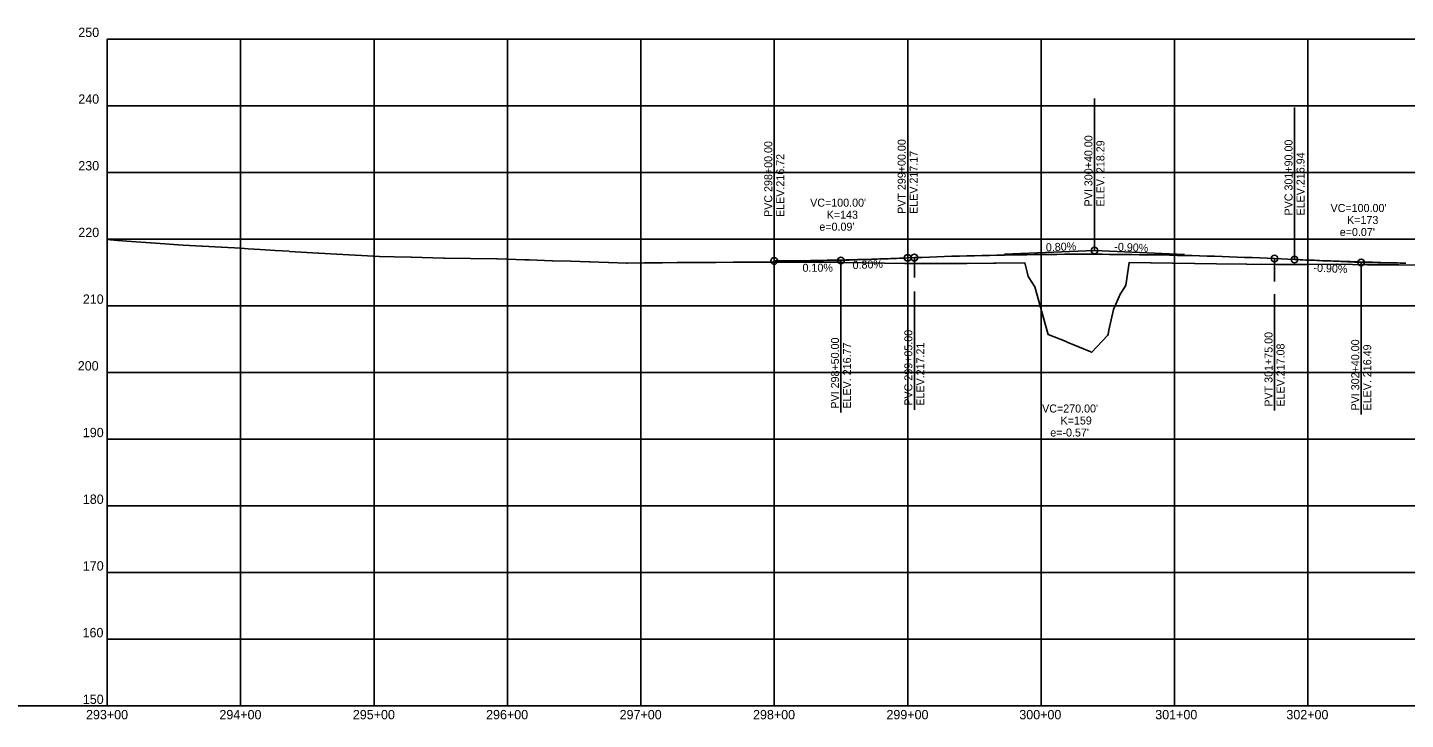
# Model space of a CAD drawing. Extents: x 1138442 to 1165793, y 1654070 to 1657687.
# Drawn here: x 1163494 to 1164527, y 1654670 to 1655189 of the extents above; entities that cross this region are included whole.
import ezdxf

# ---------------------------------------------------------------- set-up
doc = ezdxf.new("R2010")
doc.units = 0
for name, color, linetype in [('B_Dimensions', 7, 'Continuous'), ('R_Axis', 7, 'Continuous'), ('R_Axis Annot', 7, 'Continuous'), ('R_Grid', 7, 'Continuous'), ('R_Horz Alg Annot', 7, 'Continuous'), ('R_No Plot', 7, 'Continuous'), ('R_Proposed Const Limits_Hand', 7, 'Continuous'), ('R_Vert Alg Annot', 7, 'Continuous')]:
    doc.layers.add(name, color=color, linetype=linetype)

msp = doc.modelspace()

# ---------------------------------------------------------------- linework, layer by layer
at = {"layer": 'B_Dimensions'}
for p, q in [((1164153.6, 1655016.3), (1164158.6, 1655016.5)), ((1164226.1, 1655019.2), (1164293.6, 1655021.9)), ((1164293.6, 1655021.9), (1164361.1, 1655018.8)), ((1164428.6, 1655015.8), (1164443.6, 1655015.1)), ((1164078.6, 1655014.1), (1164103.6, 1655014.3)), ((1164103.6, 1655014.3), (1164128.6, 1655015.3)), ((1164468.6, 1655014), (1164493.6, 1655012.9)), ((1164493.6, 1655012.9), (1164518.6, 1655012.4))]:
    msp.add_line(p, q, dxfattribs=at)
for points in [[(1164053.6, 1655014), (1164055.7, 1655014), (1164057.8, 1655014), (1164059.9, 1655014), (1164062, 1655014.1), (1164064, 1655014.1), (1164066.1, 1655014.1), (1164068.2, 1655014.1), (1164070.3, 1655014.1), (1164072.4, 1655014.2), (1164074.5, 1655014.2), (1164076.5, 1655014.2), (1164078.6, 1655014.2), (1164080.7, 1655014.3), (1164082.8, 1655014.3), (1164084.9, 1655014.3), (1164087, 1655014.4), (1164089, 1655014.4), (1164091.1, 1655014.4), (1164093.2, 1655014.5), (1164095.3, 1655014.5), (1164097.4, 1655014.6), (1164099.5, 1655014.6), (1164101.5, 1655014.6), (1164105.7, 1655014.7), (1164107.8, 1655014.8), (1164109.9, 1655014.8), (1164112, 1655014.9), (1164114, 1655014.9), (1164116.1, 1655015), (1164118.2, 1655015.1), (1164120.3, 1655015.1), (1164122.4, 1655015.2), (1164124.5, 1655015.2), (1164126.5, 1655015.3), (1164128.6, 1655015.4), (1164130.7, 1655015.4), (1164132.8, 1655015.5), (1164134.9, 1655015.6), (1164137, 1655015.6), (1164139, 1655015.7), (1164141.1, 1655015.8), (1164143.2, 1655015.9), (1164145.3, 1655015.9), (1164147.4, 1655016), (1164149.5, 1655016.1), (1164151.5, 1655016.2), (1164153.6, 1655016.3)], [(1164158.6, 1655016.5), (1164164.3, 1655016.7), (1164169.9, 1655016.9), (1164175.5, 1655017.1), (1164181.1, 1655017.3), (1164186.8, 1655017.5), (1164192.4, 1655017.6), (1164198, 1655017.8), (1164203.6, 1655017.9), (1164209.3, 1655018.1), (1164214.9, 1655018.2), (1164220.5, 1655018.3), (1164226.1, 1655018.4), (1164231.8, 1655018.5), (1164237.4, 1655018.6), (1164243, 1655018.7), (1164248.6, 1655018.8), (1164254.3, 1655018.8), (1164259.9, 1655018.9), (1164265.5, 1655018.9), (1164271.1, 1655019), (1164276.8, 1655019), (1164282.4, 1655019), (1164288, 1655019), (1164299.3, 1655019), (1164304.9, 1655018.9), (1164310.5, 1655018.9), (1164316.1, 1655018.8), (1164321.8, 1655018.8), (1164327.4, 1655018.7), (1164333, 1655018.6), (1164338.6, 1655018.6), (1164344.3, 1655018.5), (1164349.9, 1655018.3), (1164355.5, 1655018.2), (1164361.1, 1655018.1), (1164366.8, 1655018), (1164372.4, 1655017.8), (1164378, 1655017.7), (1164383.6, 1655017.5), (1164389.3, 1655017.3), (1164394.9, 1655017.1), (1164400.5, 1655016.9), (1164406.1, 1655016.7), (1164411.8, 1655016.5), (1164417.4, 1655016.3), (1164423, 1655016), (1164428.6, 1655015.8)], [(1164443.6, 1655015.1), (1164445.7, 1655015), (1164447.8, 1655014.9), (1164449.9, 1655014.8), (1164452, 1655014.7), (1164454, 1655014.6), (1164456.1, 1655014.6), (1164458.2, 1655014.5), (1164460.3, 1655014.4), (1164462.4, 1655014.3), (1164464.5, 1655014.2), (1164466.5, 1655014.1), (1164468.6, 1655014.1), (1164470.7, 1655014), (1164472.8, 1655013.9), (1164474.9, 1655013.8), (1164477, 1655013.8), (1164479, 1655013.7), (1164481.1, 1655013.6), (1164483.2, 1655013.5), (1164485.3, 1655013.5), (1164487.4, 1655013.4), (1164489.5, 1655013.3), (1164491.5, 1655013.3), (1164495.7, 1655013.2), (1164497.8, 1655013.1), (1164499.9, 1655013), (1164502, 1655013), (1164504, 1655012.9), (1164506.1, 1655012.9), (1164508.2, 1655012.8), (1164510.3, 1655012.7), (1164512.4, 1655012.7), (1164514.5, 1655012.6), (1164516.5, 1655012.6), (1164518.6, 1655012.5), (1164520.7, 1655012.5), (1164522.8, 1655012.4), (1164524.9, 1655012.4), (1164527, 1655012.4)]]:
    msp.add_lwpolyline(points, dxfattribs=at)
at = {"layer": 'R_Axis'}
for q in [(1163553.6, 1655180.4), (1165053.6, 1654680.4)]:
    msp.add_line((1163553.6, 1654680.4), q, dxfattribs=at)
at = {"layer": 'R_Grid'}
for p, q in [((1163553.6, 1655180.4), (1165053.6, 1655180.4)), ((1163553.6, 1655180.4), (1165053.6, 1655180.4)), ((1163653.6, 1654680.4), (1163653.6, 1655180.4)), ((1163753.6, 1654680.4), (1163753.6, 1655180.4)), ((1163853.6, 1654680.4), (1163853.6, 1655180.4)), ((1163953.6, 1654680.4), (1163953.6, 1655180.4)), ((1164053.6, 1654680.4), (1164053.6, 1655180.4)), ((1164153.6, 1654680.4), (1164153.6, 1655180.4)), ((1164253.6, 1654680.4), (1164253.6, 1655180.4)), ((1164353.6, 1654680.4), (1164353.6, 1655180.4)), ((1164453.6, 1654680.4), (1164453.6, 1655180.4)), ((1163553.6, 1655130.4), (1165053.6, 1655130.4)), ((1163553.6, 1655080.4), (1165053.6, 1655080.4)), ((1163553.6, 1655030.4), (1165053.6, 1655030.4)), ((1163553.6, 1654980.4), (1165053.6, 1654980.4)), ((1163553.6, 1654930.4), (1165053.6, 1654930.4)), ((1163553.6, 1654880.4), (1165053.6, 1654880.4)), ((1163553.6, 1654830.4), (1165053.6, 1654830.4)), ((1163553.6, 1654780.4), (1165053.6, 1654780.4)), ((1163553.6, 1654730.4), (1165053.6, 1654730.4))]:
    msp.add_line(p, q, dxfattribs=at)
at = {"layer": 'R_No Plot'}
msp.add_line((1163553.6, 1654680.4), (1161984.5, 1654680.4), dxfattribs=at)
at = {"layer": 'R_Proposed Const Limits_Hand'}
msp.add_lwpolyline([(1163553.6, 1655030), (1163561.2, 1655029.4), (1163561.4, 1655029.4), (1163571.7, 1655028.7), (1163585.9, 1655027.7), (1163586.3, 1655027.7), (1163610.4, 1655025.9), (1163624.4, 1655025.1), (1163624.9, 1655025.1), (1163639, 1655024.3), (1163639.3, 1655024.3), (1163653.7, 1655023.5), (1163653.7, 1655023.5), (1163659.3, 1655023.1), (1163668.1, 1655022.6), (1163668.2, 1655022.6), (1163668.3, 1655022.6), (1163679.4, 1655021.9), (1163690, 1655021.3), (1163690.1, 1655021.2), (1163711.6, 1655019.9), (1163712.1, 1655019.9), (1163734.6, 1655018.6), (1163734.7, 1655018.6), (1163744.3, 1655018.1), (1163757.4, 1655017.3), (1163757.6, 1655017.3), (1163768.7, 1655017.1), (1163781.3, 1655016.8), (1163781.5, 1655016.8), (1163781.7, 1655016.8), (1163805.6, 1655016.2), (1163806.3, 1655016.2), (1163825.9, 1655015.9), (1163845.6, 1655015.5), (1163846.2, 1655015.5), (1163866.5, 1655014.9), (1163866.6, 1655014.9), (1163869.9, 1655014.8), (1163887.1, 1655014.2), (1163887.4, 1655014.2), (1163901.1, 1655013.8), (1163901.1, 1655013.8), (1163901.1, 1655013.8), (1163914.8, 1655013.3), (1163915, 1655013.3), (1163915.3, 1655013.3), (1163929, 1655012.9), (1163929.5, 1655012.8), (1163942.9, 1655012.4), (1163943.6, 1655012.4), (1163956.2, 1655012.5), (1163956.7, 1655012.5), (1163969.6, 1655012.7), (1163969.8, 1655012.7), (1163980.8, 1655012.8), (1163983, 1655012.8), (1163983, 1655012.8), (1163996.3, 1655012.9), (1163996.6, 1655012.9), (1164009.6, 1655012.9), (1164009.8, 1655012.9), (1164022.9, 1655013), (1164023, 1655013), (1164036.2, 1655013.1), (1164036.3, 1655013.1), (1164049.5, 1655013.1), (1164049.5, 1655013.1), (1164070, 1655013), (1164089.6, 1655013), (1164090.5, 1655013), (1164105.3, 1655012.8), (1164105.8, 1655012.8), (1164120.7, 1655012.5), (1164121.1, 1655012.5), (1164136.1, 1655012.3), (1164136.3, 1655012.3), (1164151.5, 1655012.1), (1164151.6, 1655012.1), (1164174.7, 1655012), (1164174.8, 1655012), (1164174.8, 1655012), (1164180.4, 1655012), (1164197.9, 1655012), (1164198, 1655012), (1164217.9, 1655012.3), (1164219.7, 1655012.3), (1164219.7, 1655012.3), (1164241.4, 1655012.7), (1164243.2, 1655005.6), (1164244, 1655002.4), (1164244, 1655002.3), (1164244.4, 1655001.7), (1164248.8, 1654994.7), (1164248.8, 1654994.5), (1164258.7, 1654959.6), (1164258.9, 1654959), (1164272.3, 1654953.6), (1164273.1, 1654953.1), (1164290.9, 1654945.8), (1164291.5, 1654945.4), (1164303.3, 1654958.1), (1164303.9, 1654959), (1164304.5, 1654962.2), (1164307.8, 1654977.5), (1164313.2, 1654989.6), (1164313.3, 1654989.8), (1164316.1, 1654994.1), (1164317.1, 1654995.8), (1164317.2, 1654995.9), (1164317.6, 1654999.2), (1164319.7, 1655012.9), (1164319.7, 1655012.9), (1164319.7, 1655012.9), (1164335.7, 1655012.6), (1164336.1, 1655012.6), (1164352.2, 1655012.3), (1164352.4, 1655012.3), (1164368.6, 1655012.1), (1164368.8, 1655012.1), (1164385.1, 1655011.8), (1164385.1, 1655011.8), (1164385.2, 1655011.8), (1164407.5, 1655011.5), (1164407.8, 1655011.5), (1164429.8, 1655011.3), (1164430.5, 1655011.3), (1164452.8, 1655011.4), (1164475.4, 1655011.5), (1164475.8, 1655011.5), (1164498.4, 1655011.2), (1164498.8, 1655011.2), (1164521.3, 1655011), (1164521.8, 1655011), (1164542.3, 1655010.8)], dxfattribs=at)
at = {"layer": 'R_Vert Alg Annot'}
for p, q in [((1164153.6, 1655046.3), (1164153.6, 1655130.3)), ((1164293.6, 1655051.9), (1164293.6, 1655135.9)), ((1164443.6, 1655045.1), (1164443.6, 1655129.1)), ((1164053.6, 1655044), (1164053.6, 1655128)), ((1164293.6, 1655021.9), (1164293.6, 1655051.9)), ((1164053.6, 1655014), (1164053.6, 1655044)), ((1164153.6, 1655016.3), (1164153.6, 1655046.3)), ((1164443.6, 1655015.1), (1164443.6, 1655045.1)), ((1164158.6, 1655016.5), (1164158.6, 1655001.5)), ((1164428.6, 1655015.8), (1164428.6, 1654998.5)), ((1164103.6, 1655014.3), (1164103.6, 1654984.3)), ((1164493.6, 1655012.9), (1164493.6, 1654982.9)), ((1164158.6, 1654991.2), (1164158.6, 1654986.5)), ((1164158.6, 1654986.5), (1164158.6, 1654902.5)), ((1164428.6, 1654989), (1164428.6, 1654985.8)), ((1164428.6, 1654985.8), (1164428.6, 1654901.8)), ((1164103.6, 1654984.3), (1164103.6, 1654900.3)), ((1164493.6, 1654982.9), (1164493.6, 1654898.9))]:
    msp.add_line(p, q, dxfattribs=at)
for centre in [(1164053.6, 1655014), (1164103.6, 1655014.3), (1164153.6, 1655016.3), (1164158.6, 1655016.5), (1164293.6, 1655021.9), (1164428.6, 1655015.8), (1164443.6, 1655015.1), (1164493.6, 1655012.9)]:
    msp.add_circle(centre, 2.5, dxfattribs=at)

# ---------------------------------------------------------------- texts
at = {"layer": 'R_Axis Annot'}
for s, height, p in [('250', 7, (1163531.9, 1655181.9)), ('250', 7, (1163531.9, 1655181.9)), ('240', 7, (1163531.9, 1655131.9)), ('230', 7, (1163531.9, 1655081.9)), ('220', 7, (1163531.9, 1655031.9)), ('210', 7, (1163535.3, 1654981.9)), ('200', 7, (1163531.5, 1654931.9)), ('190', 7, (1163535.3, 1654881.9)), ('180', 7, (1163535.3, 1654831.9)), ('170', 7, (1163535.3, 1654781.9)), ('160', 7, (1163535.1, 1654731.9)), ('150', 7, (1163535.3, 1654681.9)), ('293+00', 7, (1163537.7, 1654670.4)), ('-', 0.0001, (1163553.6, 1654680.4)), ('294+00', 7, (1163637.7, 1654670.4)), ('295+00', 7, (1163737.7, 1654670.4)), ('296+00', 7, (1163837.6, 1654670.4)), ('297+00', 7, (1163937.7, 1654670.4)), ('298+00', 7, (1164037.7, 1654670.4)), ('299+00', 7, (1164137.7, 1654670.4)), ('300+00', 7, (1164237.3, 1654670.4)), ('301+00', 7, (1164339.2, 1654670.4)), ('302+00', 7, (1164437.5, 1654670.4))]:
    msp.add_text(s, height=height, dxfattribs=at).set_placement(p)
at = {"layer": 'R_Horz Alg Annot'}
for s, rotation, p in [('0.10%', 0.2865, (1164074.8, 1655005.9)), ('0.80%', 2.2906, (1164112.4, 1655007.9)), ('-0.90%', 357.4234, (1164457.7, 1655006))]:
    msp.add_text(s, height=6, rotation=rotation, dxfattribs=at).set_placement(p)
at = {"layer": 'R_Vert Alg Annot'}
for s, rotation, p in [('PVC 298+00.00', 90, (1164052.1, 1655047)), ('PVT 299+00.00', 90, (1164152.1, 1655049.3)), ('PVI 300+40.00', 90, (1164292.1, 1655054.9)), ('ELEV. 218.29', 90, (1164301.1, 1655054.9)), ('PVC 301+90.00', 90, (1164442.1, 1655048.1)), ('ELEV.216.72', 90, (1164061.1, 1655047)), ('ELEV.217.17', 90, (1164161.1, 1655049.3)), ('ELEV.216.94', 90, (1164451.1, 1655048.1)), ('0.80%', 2.2906, (1164257.3, 1655021.2)), ('-0.90%', 357.4234, (1164308.4, 1655021.8)), ('PVI 298+50.00', 90, (1164102.1, 1654903.3)), ('PVC 299+05.00', 90, (1164157.1, 1654905.5)), ('PVT 301+75.00', 90, (1164427.1, 1654904.8)), ('PVI 302+40.00', 90, (1164492.1, 1654901.9)), ('ELEV. 216.77', 90, (1164111.1, 1654903.3)), ('ELEV.217.21', 90, (1164166.1, 1654905.5)), ('ELEV.217.08', 90, (1164436.1, 1654904.8)), ('ELEV. 216.49', 90, (1164501.1, 1654901.9))]:
    msp.add_text(s, height=6, rotation=rotation, dxfattribs=at).set_placement(p)
for s, p in [("VC=100.00'", (1164080.5, 1655054.7)), ("VC=100.00'", (1164470.6, 1655050.7)), ('K=143', (1164092.9, 1655045.7)), ('K=173', (1164483, 1655041.7)), ("e=0.09'", (1164087.4, 1655036.7)), ("e=0.07'", (1164477.5, 1655032.7)), ("VC=270.00'", (1164254.4, 1654900.4)), ('K=159', (1164268.2, 1654891.4)), ("e=-0.57'", (1164260.5, 1654882.4))]:
    msp.add_text(s, height=6, dxfattribs=at).set_placement(p)

doc.saveas('drawing.dxf')
